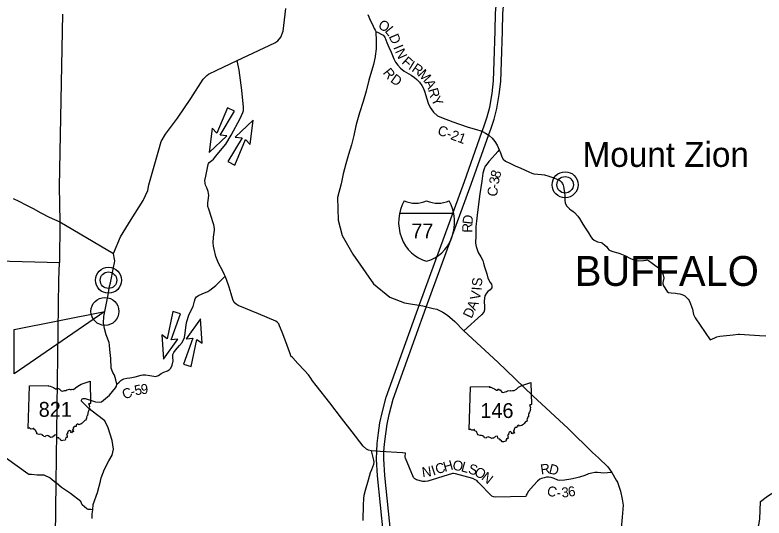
# Model space of a CAD drawing. Extents: x 0 to 34, y 0 to 22.
# Drawn here: x 24.277 to 28.547, y 14.868 to 17.734 of the extents above; entities that cross this region are included whole.
import ezdxf

# ---------------------------------------------------------------- set-up
doc = ezdxf.new("R2010")
doc.units = 0
for name, color, linetype in [('Default', 7, 'Continuous'), ('GM_X_County_Road', 7, 'Continuous'), ('GM_X_County_Road_Text', 7, 'Continuous'), ('GM_X_Major_River', 7, 'Continuous'), ('GM_X_State_Route', 7, 'Continuous'), ('GM_X_Township', 7, 'Continuous'), ('GM_X_Unincorporated', 7, 'Continuous'), ('GM_X_Unincorporated_Text', 7, 'Continuous'), ('TX_P_1', 7, 'Continuous')]:
    doc.layers.add(name, color=color, linetype=linetype)

msp = doc.modelspace()

# ---------------------------------------------------------------- linework, layer by layer
at = {"layer": 'Default'}
for p, q in [((24.3527, 15.3778), (24.3606, 15.6218)), ((26.8657, 15.371), (26.8735, 15.615))]:
    msp.add_line(p, q, dxfattribs=at)
for points in [[(26.3336, 17.6392), (26.343, 17.6361), (26.3692, 17.6237), (26.3767, 17.6184), (26.3857, 17.6081), (26.3971, 17.5769), (26.4074, 17.5504), (26.4207, 17.5226), (26.4365, 17.4842), (26.4465, 17.4652), (26.4591, 17.4473), (26.4741, 17.4317), (26.4962, 17.4144), (26.5351, 17.3902), (26.5554, 17.3772), (26.5677, 17.3661), (26.5827, 17.3504), (26.5964, 17.3329), (26.6035, 17.3196), (26.6116, 17.2991), (26.624, 17.2562), (26.6324, 17.2319), (26.6446, 17.2064), (26.6636, 17.1805), (26.6864, 17.1603), (26.7093, 17.1491), (26.7724, 17.1261), (26.854, 17.0958), (26.9127, 17.0805), (26.9277, 17.0754), (26.9412, 17.0692), (26.9588, 17.0602), (26.9806, 17.0473), (26.9963, 17.032), (27.0131, 17.0122), (27.025, 16.9928), (27.0379, 16.9662)], [(25.4746, 16.2459), (25.4722, 16.2542), (25.4611, 16.2741), (25.4378, 16.3201), (25.4224, 16.3575), (25.4119, 16.3994), (25.4084, 16.4168), (25.4067, 16.4357), (25.4095, 16.4679), (25.4149, 16.5088), (25.4152, 16.5171), (25.4102, 16.5387), (25.392, 16.5972), (25.3885, 16.6104), (25.3823, 16.6281), (25.377, 16.6425), (25.3765, 16.6531), (25.3768, 16.6641), (25.38, 16.6906), (25.3818, 16.7069), (25.381, 16.7175), (25.3786, 16.7284), (25.3709, 16.7495), (25.3629, 16.7642), (25.3606, 16.7758), (25.3585, 16.791), (25.3644, 16.8159), (25.3787, 16.8827), (25.3802, 16.8869), (25.3844, 16.8933), (25.3913, 16.8996), (25.3996, 16.9056), (25.4091, 16.9127), (25.4218, 16.9288), (25.468, 16.984), (25.479, 16.9975), (25.5097, 17.0491), (25.5601, 17.145), (25.5763, 17.1782), (25.5798, 17.1906), (25.58, 17.208), (25.5697, 17.3065), (25.5542, 17.419), (25.5441, 17.4745)], [(27.0379, 16.9662), (27.0288, 16.9568), (26.9829, 16.9035), (26.9792, 16.8992)], [(27.0379, 16.9662), (27.0423, 16.954), (27.0478, 16.9373), (27.053, 16.9252), (27.0604, 16.9126), (27.0735, 16.9015), (27.0979, 16.8888), (27.129, 16.8741), (27.1598, 16.8609), (27.2053, 16.8397), (27.2233, 16.8319), (27.2342, 16.8292), (27.2579, 16.8267), (27.2779, 16.8254), (27.2949, 16.8225), (27.3201, 16.8151), (27.3494, 16.8065), (27.3667, 16.7991), (27.3768, 16.7945), (27.3837, 16.7901), (27.3906, 16.7828), (27.3981, 16.7746), (27.4012, 16.7648), (27.404, 16.7559)], [(26.9792, 16.8992), (26.9791, 16.899), (26.9681, 16.8863), (26.9581, 16.872), (26.9508, 16.8573), (26.9437, 16.8324), (26.9384, 16.7867), (26.9262, 16.7147), (26.9137, 16.6104), (26.9074, 16.5592), (26.9045, 16.5281), (26.9039, 16.4774), (26.9027, 16.4331), (26.9053, 16.4146), (26.9172, 16.3811), (26.9332, 16.356), (26.9434, 16.3343), (26.9478, 16.3203), (26.9542, 16.2996), (26.9662, 16.2582), (26.9734, 16.2349), (26.986, 16.2101), (26.9926, 16.2), (26.9961, 16.1883), (26.9959, 16.1789), (26.9859, 16.1674), (26.9721, 16.1576), (26.9643, 16.1492), (26.9551, 16.1343), (26.9515, 16.1047), (26.9536, 16.0691), (26.9528, 16.0532), (26.9503, 16.0403), (26.9362, 16.0264), (26.8359, 15.9347)], [(27.404, 16.7559), (27.4064, 16.7457), (27.4103, 16.72), (27.412, 16.7053), (27.4112, 16.686), (27.411, 16.6765), (27.4139, 16.663), (27.4214, 16.6468), (27.4372, 16.6301), (27.4475, 16.6219), (27.4567, 16.6164), (27.4663, 16.6083), (27.4847, 16.5885), (27.4952, 16.5736), (27.5084, 16.5522), (27.5243, 16.5275), (27.5457, 16.492), (27.559, 16.4706), (27.5678, 16.4606), (27.579, 16.4509), (27.5976, 16.4422), (27.6185, 16.4373), (27.6254, 16.434), (27.6403, 16.4233), (27.6503, 16.4125), (27.6569, 16.4043), (27.6623, 16.3968), (27.6707, 16.3916), (27.6855, 16.3858), (27.7144, 16.3792), (27.7246, 16.3752), (27.7528, 16.3643), (27.7852, 16.3468), (27.805, 16.3384), (27.8168, 16.3371), (27.8315, 16.334), (27.8591, 16.3345), (27.8746, 16.3378), (27.8798, 16.3386), (27.8875, 16.3354), (27.91, 16.3191), (27.9537, 16.287), (27.9595, 16.281), (27.9677, 16.2653), (27.9724, 16.2521), (27.9748, 16.2442), (27.975, 16.2336), (27.9715, 16.218), (27.9701, 16.2097), (27.9706, 16.2017), (27.9735, 16.1908), (27.9952, 16.1583), (28.0032, 16.1531), (28.0169, 16.1507), (28.0426, 16.1485), (28.0525, 16.1468), (28.0665, 16.1448), (28.0832, 16.1398), (28.0946, 16.1347), (28.1043, 16.125), (28.1139, 16.115), (28.1197, 16.1067), (28.1287, 16.088), (28.1383, 16.0579), (28.1424, 16.0364), (28.1452, 16.0273), (28.1546, 16.0093), (28.2395, 15.8837), (28.2501, 15.8865), (28.2696, 15.8963), (28.2782, 15.9003), (28.2959, 15.9036), (28.3702, 15.9125), (28.3989, 15.9153), (28.4076, 15.9162), (28.5215, 15.9069), (28.557, 15.9064)], [(24.2666, 16.6893), (24.2993, 16.6724), (24.3429, 16.6507), (24.3816, 16.6308), (24.4253, 16.6075), (24.4723, 16.582), (24.5329, 16.556)], [(24.5329, 16.556), (24.8396, 16.3747)], [(24.8568, 15.6314), (24.8705, 15.6419), (24.8807, 15.6515), (24.8859, 15.6557), (24.8976, 15.6603), (24.9149, 15.665), (24.9327, 15.6663), (24.9433, 15.6679), (24.9617, 15.6714), (24.9972, 15.6823), (25.0055, 15.6839), (25.0202, 15.684), (25.0467, 15.6808), (25.0686, 15.6757), (25.0766, 15.675), (25.0841, 15.6758), (25.0958, 15.6808), (25.1105, 15.6904), (25.1251, 15.6988), (25.147, 15.7073), (25.1564, 15.712), (25.1658, 15.7211), (25.1729, 15.7382), (25.1783, 15.764), (25.1767, 15.7844), (25.1773, 15.7988), (25.1818, 15.8113), (25.193, 15.8247), (25.2155, 15.8502), (25.2305, 15.8685), (25.2428, 15.8962), (25.2475, 15.9205), (25.2525, 15.9678), (25.2565, 15.9879), (25.2687, 16.024), (25.2784, 16.0441), (25.2922, 16.0726), (25.301, 16.1029), (25.3043, 16.117), (25.3114, 16.1276), (25.3223, 16.1364), (25.3449, 16.1457), (25.3758, 16.1588), (25.3882, 16.1657), (25.4213, 16.1936), (25.4746, 16.2459)], [(26.504, 15.2085), (26.5039, 15.2086), (26.5019, 15.2132), (26.5011, 15.2181), (26.5025, 15.2382), (26.4866, 15.2396), (26.3596, 15.2475), (26.309, 15.2507), (26.2931, 15.2547), (26.2817, 15.2599), (26.2623, 15.2779), (26.1983, 15.3588), (26.1384, 15.4363), (26.0721, 15.5232), (25.9935, 15.6229), (25.9733, 15.6503), (25.963, 15.6639), (25.9493, 15.6831), (25.9279, 15.709), (25.8899, 15.7481), (25.8602, 15.78), (25.8571, 15.7842), (25.8503, 15.7909), (25.848, 15.7996), (25.8383, 15.8237), (25.8275, 15.8573), (25.8006, 15.926), (25.7856, 15.9634), (25.7802, 15.9735), (25.7741, 15.9822), (25.7643, 15.9889), (25.665, 16.0313), (25.5498, 16.0796), (25.5373, 16.0867), (25.5262, 16.0957), (25.5182, 16.1126), (25.51, 16.1451), (25.4984, 16.184), (25.4822, 16.2278), (25.4746, 16.2459)], [(24.3606, 15.6218), (24.4687, 15.6233), (24.4671, 15.6204), (24.4772, 15.6198), (24.4881, 15.6146), (24.4973, 15.6113), (24.5084, 15.6036), (24.5152, 15.6036), (24.518, 15.61), (24.5231, 15.6051), (24.5293, 15.6042), (24.5398, 15.5925), (24.5486, 15.59), (24.559, 15.594), (24.5667, 15.5947), (24.5724, 15.5986), (24.5873, 15.602), (24.5915, 15.5999), (24.5993, 15.6004), (24.6033, 15.6019), (24.6102, 15.6005), (24.6221, 15.6094), (24.6346, 15.6199), (24.6537, 15.6298), (24.6822, 15.6391), (24.7048, 15.6474), (24.7081, 15.5208)], [(26.8735, 15.615), (26.9817, 15.6166), (26.98, 15.6136), (26.9902, 15.613), (27.0011, 15.6078), (27.0102, 15.6045), (27.0214, 15.5968), (27.0281, 15.5968), (27.031, 15.6032), (27.0361, 15.5983), (27.0422, 15.5974), (27.0528, 15.5857), (27.0615, 15.5832), (27.072, 15.5872), (27.0797, 15.5879), (27.0854, 15.5918), (27.1003, 15.5952), (27.1044, 15.5932), (27.1123, 15.5936), (27.1163, 15.5951), (27.1231, 15.5938), (27.1351, 15.6027), (27.1476, 15.6131), (27.1667, 15.623), (27.1952, 15.6323), (27.2178, 15.6407), (27.2211, 15.514)], [(24.7081, 15.5208), (24.7048, 15.519), (24.6996, 15.5198), (24.6961, 15.5164), (24.7004, 15.5104), (24.7024, 15.5041), (24.7006, 15.4973), (24.7024, 15.4916), (24.7012, 15.4868), (24.698, 15.482), (24.6968, 15.4775), (24.6941, 15.4728), (24.6943, 15.4701), (24.6917, 15.468), (24.6921, 15.4601), (24.6908, 15.4557), (24.6913, 15.4519), (24.6869, 15.4509), (24.6879, 15.4478), (24.6852, 15.4453), (24.6858, 15.4412), (24.6827, 15.4385), (24.6857, 15.4332), (24.6833, 15.4315), (24.6813, 15.4251), (24.6758, 15.4237), (24.6648, 15.412), (24.6609, 15.4075), (24.6566, 15.4064), (24.6541, 15.4018), (24.6488, 15.4018), (24.6406, 15.3986), (24.6354, 15.4041), (24.6262, 15.3975), (24.6251, 15.3899), (24.6136, 15.3901), (24.614, 15.3863), (24.6114, 15.3851), (24.609, 15.3813), (24.6104, 15.3744), (24.6049, 15.3727), (24.6056, 15.3687), (24.6091, 15.3663), (24.6106, 15.3587), (24.6048, 15.3602), (24.6001, 15.3538), (24.5952, 15.3553), (24.5968, 15.3608), (24.5885, 15.3673), (24.5808, 15.3621), (24.5767, 15.3537), (24.5766, 15.3481), (24.5708, 15.3447), (24.5746, 15.3368), (24.5738, 15.3313), (24.574, 15.3261), (24.5667, 15.3263), (24.5623, 15.3123)], [(27.2211, 15.514), (27.2177, 15.5123), (27.2126, 15.5131), (27.2091, 15.5096), (27.2134, 15.5036), (27.2154, 15.4974), (27.2136, 15.4905), (27.2154, 15.4848), (27.2142, 15.48), (27.211, 15.4752), (27.2098, 15.4708), (27.207, 15.466), (27.2072, 15.4633), (27.2046, 15.4613), (27.2051, 15.4533), (27.2038, 15.4489), (27.2042, 15.4451), (27.1999, 15.4442), (27.2009, 15.441), (27.1982, 15.4386), (27.1988, 15.4344), (27.1957, 15.4318), (27.1986, 15.4265), (27.1963, 15.4248), (27.1943, 15.4183), (27.1887, 15.417), (27.1778, 15.4052), (27.1739, 15.4007), (27.1696, 15.3996), (27.1671, 15.395), (27.1618, 15.395), (27.1536, 15.3918), (27.1484, 15.3973), (27.1392, 15.3907), (27.1381, 15.3831), (27.1265, 15.3833), (27.1269, 15.3795), (27.1243, 15.3784), (27.122, 15.3745), (27.1233, 15.3677), (27.1179, 15.3659), (27.1185, 15.362), (27.1221, 15.3596), (27.1236, 15.3519), (27.1178, 15.3535), (27.1131, 15.3471), (27.1082, 15.3486), (27.1098, 15.354), (27.1015, 15.3606), (27.0937, 15.3553), (27.0897, 15.3469), (27.0896, 15.3413), (27.0838, 15.3379), (27.0875, 15.33), (27.0868, 15.3245), (27.0869, 15.3193), (27.0797, 15.3195), (27.0752, 15.3055)], [(24.5623, 15.3123), (24.5497, 15.3096), (24.541, 15.308), (24.5378, 15.3144), (24.5316, 15.3177), (24.5275, 15.3241), (24.5185, 15.325), (24.5164, 15.3338), (24.5154, 15.3409), (24.5031, 15.3392), (24.4997, 15.3348), (24.4953, 15.3336), (24.4928, 15.3292), (24.4868, 15.3289), (24.4804, 15.3268), (24.4762, 15.3311), (24.4658, 15.3354), (24.4611, 15.3376), (24.4512, 15.3342), (24.4492, 15.3301), (24.4414, 15.3319), (24.4395, 15.3365), (24.4348, 15.3379), (24.4337, 15.3427), (24.4236, 15.3453), (24.4158, 15.3443), (24.4022, 15.3482), (24.4013, 15.3546), (24.3967, 15.3624), (24.3943, 15.3678), (24.3857, 15.3719), (24.3839, 15.3783), (24.3812, 15.3782), (24.3786, 15.3755), (24.369, 15.3743), (24.3652, 15.3769), (24.3598, 15.3815), (24.3527, 15.3778)], [(27.0752, 15.3055), (27.0627, 15.3028), (27.0539, 15.3012), (27.0508, 15.3076), (27.0446, 15.311), (27.0404, 15.3173), (27.0315, 15.3182), (27.0293, 15.327), (27.0283, 15.3341), (27.016, 15.3324), (27.0127, 15.328), (27.0083, 15.3269), (27.0058, 15.3224), (26.9998, 15.3221), (26.9934, 15.32), (26.9892, 15.3243), (26.9788, 15.3287), (26.974, 15.3309), (26.9642, 15.3274), (26.9621, 15.3233), (26.9544, 15.3251), (26.9525, 15.3297), (26.9478, 15.3311), (26.9467, 15.3359), (26.9366, 15.3386), (26.9288, 15.3375), (26.9152, 15.3414), (26.9143, 15.3478), (26.9096, 15.3556), (26.9073, 15.361), (26.8987, 15.3651), (26.8969, 15.3716), (26.8941, 15.3714), (26.8916, 15.3688), (26.882, 15.3675), (26.8782, 15.3702), (26.8728, 15.3747), (26.8657, 15.371)], [(26.2626, 14.854), (26.2639, 14.943), (26.2652, 14.9778), (26.2684, 14.9983), (26.275, 15.026), (26.2924, 15.0848), (26.3042, 15.1269), (26.312, 15.1451), (26.3235, 15.1747), (26.3253, 15.1842), (26.3233, 15.1978), (26.3148, 15.2272), (26.309, 15.2507)], [(24.2294, 15.2095), (24.3496, 15.122), (24.3561, 15.1184), (24.3716, 15.1183), (24.4042, 15.1143), (24.4419, 15.1146), (24.4786, 15.097), (24.5114, 15.0682)], [(27.6786, 15.128), (27.6553, 15.125), (27.6311, 15.1236), (27.6175, 15.1247), (27.5975, 15.1268), (27.5831, 15.1263), (27.5658, 15.1239), (27.5461, 15.1188), (27.525, 15.1107), (27.4949, 15.1002), (27.4723, 15.0955), (27.4447, 15.0885), (27.4092, 15.0841), (27.3813, 15.0819), (27.3718, 15.0834), (27.3502, 15.0927), (27.3336, 15.0978), (27.3192, 15.1004), (27.3071, 15.0999), (27.2932, 15.0975), (27.2788, 15.0933), (27.2694, 15.0883), (27.2551, 15.0776), (27.2319, 15.0539), (27.2045, 15.0208), (27.1967, 15.0078), (27.1915, 14.9983), (27.1885, 14.9911), (27.0136, 14.9871), (27.0041, 14.9882), (26.9947, 14.9923), (26.9178, 15.0726), (26.909, 15.0813), (26.901, 15.0861), (26.887, 15.0928), (26.7878, 15.1204), (26.7776, 15.1219), (26.7716, 15.1211), (26.6313, 15.0783), (26.6155, 15.0752), (26.6019, 15.0755), (26.5652, 15.0854), (26.5602, 15.0884), (26.5556, 15.091), (26.5496, 15.0993), (26.504, 15.2085)], [(24.72, 14.9136), (24.7095, 14.9155), (24.7033, 14.916), (24.6935, 14.9173), (24.6871, 14.9203), (24.6593, 14.9427), (24.6517, 14.9616), (24.5941, 15.008), (24.5423, 15.0424), (24.5114, 15.0682)], [(28.5032, 14.3125), (28.5032, 14.3126), (28.5041, 14.3199), (28.5022, 14.335), (28.4942, 14.363), (28.4916, 14.3835), (28.493, 14.424), (28.4964, 14.4614), (28.4975, 14.4788), (28.4982, 14.5681), (28.497, 14.6499), (28.4955, 14.6639), (28.4856, 14.7097), (28.4811, 14.7392), (28.4811, 14.7513), (28.4837, 14.7653), (28.4973, 14.7899), (28.5094, 14.8088), (28.518, 14.8297), (28.5237, 14.8622), (28.5275, 14.9622)]]:
    msp.add_lwpolyline(points, dxfattribs=at)
for centre, major_axis, start_param, end_param in [((26.6701, 16.5539), (0, -0.2289), 4.15077, 6.05619), ((26.5597, 16.844), (0, -0.1826), 5.88324, 6.683049), ((26.5773, 16.5539), (0, -0.2289), 0.227007, 2.13242), ((26.6877, 16.844), (0, -0.1827), 5.883359, 6.683012)]:
    msp.add_ellipse(centre, major_axis=major_axis, ratio=0.9, start_param=start_param, end_param=end_param, dxfattribs=at)
at = {"layer": 'GM_X_County_Road'}
msp.add_lwpolyline([(28.5275, 14.9622), (28.5597, 14.9867), (28.5772, 14.9995), (28.5967, 15.0123), (28.6146, 15.0236), (28.6224, 15.0313), (28.6301, 15.0455), (28.6374, 15.0827), (28.6426, 15.1331), (28.6476, 15.193), (28.6535, 15.2215), (28.6702, 15.2604), (28.7008, 15.3053), (28.709, 15.3119), (28.718, 15.3169), (28.7515, 15.324), (28.7674, 15.3287), (28.7746, 15.3291)], dxfattribs=at)
at = {"layer": 'GM_X_Major_River'}
msp.add_line((26.4698, 16.6053), (26.778, 16.6053), dxfattribs=at)
at = {"layer": 'GM_X_State_Route'}
for points in [[(26.5826, 16.084), (26.839, 16.7847), (26.9392, 17.0672), (26.9517, 17.1025), (26.9691, 17.1529), (26.9833, 17.2094), (26.9966, 17.287), (27.0052, 17.3586), (27.008, 17.4687), (27.0141, 17.6436), (27.0171, 17.7452), (27.0258, 17.8505), (27.0317, 17.9388), (27.0437, 18.0148), (27.0708, 18.149), (27.0918, 18.2474)], [(26.6216, 16.0697), (26.8781, 16.7706), (26.9784, 17.0533), (26.9909, 17.0888), (27.009, 17.141), (27.024, 17.2008), (27.0378, 17.281), (27.0467, 17.3556), (27.0496, 17.4674), (27.0557, 17.6423), (27.0587, 17.7428), (27.0673, 17.8474), (27.0731, 17.9341), (27.0846, 18.0075), (27.1116, 18.1405), (27.1325, 18.2388)], [(24.8396, 16.3747), (24.8787, 16.4704), (24.9397, 16.5684), (25.0078, 16.6764), (25.0352, 16.7337), (25.0404, 16.7663), (25.0857, 16.9267), (25.0968, 16.965), (25.1111, 17.0139), (25.1353, 17.0548), (25.2034, 17.1456), (25.2795, 17.2578), (25.3504, 17.3687), (25.3709, 17.3886), (25.3804, 17.3961), (25.4275, 17.4195), (25.5441, 17.4745), (25.7584, 17.5756), (25.7749, 17.5867), (25.792, 17.6078), (25.8049, 17.6409), (25.8218, 17.7707)], [(26.2879, 17.7372), (26.3039, 17.7007), (26.3125, 17.6833), (26.3251, 17.6578), (26.3306, 17.6483), (26.3336, 17.6392), (26.336, 17.5847), (26.3364, 17.5406), (26.3308, 17.4997), (26.3308, 17.4995)], [(26.3308, 17.4995), (26.3301, 17.4948), (26.3216, 17.4519), (26.295, 17.3622), (26.2787, 17.3007), (26.2624, 17.2419), (26.2417, 17.1769), (26.226, 17.1236), (26.2199, 17.1028), (26.2088, 17.0478), (26.1951, 16.9947), (26.1791, 16.9385), (26.1631, 16.8857), (26.1483, 16.8287), (26.1372, 16.7714), (26.1159, 16.6933), (26.1193, 16.5647), (26.1427, 16.4769), (26.2027, 16.3717), (26.3209, 16.2023), (26.4137, 16.1253), (26.4974, 16.0931), (26.6021, 16.0769), (26.6605, 16.0616), (26.6818, 16.0572), (26.7153, 16.0402), (26.7425, 16.0245), (26.7847, 15.9876), (26.8345, 15.9359), (26.8359, 15.9347), (27.0302, 15.755), (27.2293, 15.5647), (27.4311, 15.3777), (27.4322, 15.3766), (27.5698, 15.2412), (27.6037, 15.2112), (27.6566, 15.159), (27.6786, 15.128), (27.7043, 15.0833), (27.7112, 15.0713), (27.7281, 15.0212), (27.7374, 14.9753), (27.7432, 14.9416), (27.7378, 14.8727), (27.7316, 14.8094)], [(24.7174, 14.8651), (24.7179, 14.8913), (24.72, 14.9136), (24.7228, 14.9447), (24.7468, 15.013), (24.7651, 15.0771), (24.7677, 15.0975), (24.7868, 15.1458), (24.8115, 15.1933), (24.8308, 15.2252), (24.839, 15.2608), (24.8316, 15.3093), (24.8075, 15.3808), (24.7892, 15.422), (24.7417, 15.4581), (24.6992, 15.4901), (24.6745, 15.5143), (24.6612, 15.5278), (24.6567, 15.5339), (24.6563, 15.54), (24.6603, 15.546), (24.666, 15.5484), (24.6781, 15.548), (24.7194, 15.5349), (24.7354, 15.5293), (24.7591, 15.5283), (24.7704, 15.5299), (24.8154, 15.567), (24.8503, 15.6092), (24.8556, 15.6191), (24.8574, 15.6282), (24.8568, 15.6314), (24.8523, 15.6549), (24.8438, 15.681), (24.8347, 15.6977), (24.8263, 15.7215), (24.8227, 15.7764), (24.8179, 15.8272), (24.8159, 15.8533), (24.814, 15.8673), (24.796, 15.9108), (24.7876, 15.9482), (24.7821, 15.9774), (24.7839, 16.016), (24.808, 16.1404), (24.8166, 16.1882), (24.8207, 16.2085), (24.8385, 16.2948), (24.8442, 16.3223), (24.8463, 16.3323), (24.8432, 16.3523), (24.8396, 16.3747)], [(26.3777, 14.7733), (26.3443, 15.1077), (26.3384, 15.2036), (26.3389, 15.2484), (26.342, 15.2925), (26.3496, 15.3538), (26.3577, 15.4106), (26.3699, 15.4676), (26.3931, 15.5566), (26.5825, 16.0839)], [(26.4192, 14.7769), (26.3858, 15.111), (26.38, 15.2047), (26.3804, 15.2466), (26.3834, 15.2884), (26.3908, 15.3483), (26.3987, 15.4034), (26.4103, 15.458), (26.4329, 15.5443), (26.6216, 16.0699)]]:
    msp.add_lwpolyline(points, dxfattribs=at)
at = {"layer": 'GM_X_Township'}
for p, q in [((24.5489, 17.738), (24.5285, 16.7562)), ((24.5285, 16.7562), (24.5329, 16.556)), ((24.5329, 16.556), (24.5317, 16.3233)), ((23.5249, 16.3502), (24.5317, 16.3233)), ((24.527, 16.2224), (24.5317, 16.3233)), ((24.527, 16.2224), (24.5317, 16.3233)), ((24.527, 16.2224), (24.5317, 16.3233)), ((24.5114, 15.0682), (24.527, 16.2224)), ((24.5114, 15.0682), (24.527, 16.2224)), ((24.5027, 14.424), (24.5114, 15.0682))]:
    msp.add_line(p, q, dxfattribs=at)
at = {"layer": 'GM_X_Unincorporated'}
for centre, radius in [((27.413, 16.7666), 0.0742), ((27.413, 16.7666), 0.0471), ((24.8101, 16.2228), 0.0742), ((24.8101, 16.2228), 0.0471)]:
    msp.add_circle(centre, radius, dxfattribs=at)
at = {"layer": 'TX_P_1'}
for points in [[(25.5282, 17.1854), (25.4882, 17.2056), (25.4271, 17.0604), (25.4016, 17.0887), (25.3844, 16.9508), (25.4852, 17.0463), (25.4473, 17.0501)], [(25.6341, 17.1341), (25.5331, 17.0385), (25.5712, 17.0346), (25.4903, 16.8994), (25.5302, 16.8792), (25.5913, 17.0244), (25.6169, 16.9962)], [(24.2721, 15.9418), (24.7897, 16.045), (24.2721, 15.69)], [(25.2201, 16.0317), (25.1769, 16.0439), (25.1449, 15.8896), (25.1144, 15.9125), (25.1242, 15.7738), (25.2047, 15.8869), (25.1668, 15.8834)], [(25.3338, 16.0018), (25.2532, 15.8886), (25.2914, 15.8921), (25.2381, 15.7438), (25.2811, 15.7316), (25.313, 15.8859), (25.3436, 15.8632)]]:
    msp.add_lwpolyline(points, close=True, dxfattribs=at)
msp.add_circle((24.7897, 16.045), 0.0797, dxfattribs=at)

# ---------------------------------------------------------------- texts
at = {"layer": 'Default'}
for s, p in [('77', (26.5362, 16.461)), ('821', (24.4123, 15.4446)), ('146', (26.9299, 15.4378))]:
    msp.add_text(s, height=0.08462, dxfattribs=at).set_placement(p)
at = {"layer": 'GM_X_County_Road_Text'}
for s, rotation, p in [('O', 333.2183, (26.3426, 17.6602)), ('L', 308.7421, (26.3822, 17.6418)), ('D', 293.013, (26.4067, 17.6122)), ('I', 292.2949, (26.4327, 17.5503)), ('N', 294.0168, (26.4423, 17.527)), ('F', 317.8384, (26.4776, 17.4607)), ('I', 328.6139, (26.5153, 17.4281)), ('R', 308.5227, (26.3715, 17.4039)), ('R', 325.7882, (26.5345, 17.4164)), ('M', 312.863, (26.5705, 17.3924)), ('D', 324.605, (26.4129, 17.3558)), ('A', 296.6433, (26.6099, 17.3508)), ('R', 286.0151, (26.6313, 17.3088)), ('Y', 295.5868, (26.6478, 17.2543)), ('C-21', 339.725, (26.681, 17.0548)), ('8', 72.1493, (27.0389, 16.7993)), ('3', 82.7498, (27.0351, 16.7673)), ('C', 80.5787, (27.0235, 16.6961)), ('-', 80.9845, (27.0312, 16.7424)), ('D', 83.7366, (26.8839, 16.5385)), ('R', 88.9774, (26.8831, 16.4933)), ('S', 85.4814, (26.9378, 16.1858)), ('V', 79.2362, (26.926, 16.1064)), ('I', 86.0564, (26.9362, 16.1627)), ('A', 65.3128, (26.9006, 16.0468)), ('D', 64.9811, (26.8793, 16.0012)), ('5', 11.5896, (24.964, 15.5659)), ('9', 5.2261, (24.9966, 15.5727)), ('C', 21.1349, (24.9008, 15.5426)), ('-', 17.9532, (24.9435, 15.5591)), ('N', 7.6397, (26.6002, 15.1001)), ('I', 18.5685, (26.6611, 15.1094)), ('C', 17.0944, (26.6828, 15.1167)), ('H', 15.7673, (26.727, 15.1303)), ('O', 350.1304, (26.7684, 15.1435)), ('L', 344.5261, (26.8161, 15.1352)), ('S', 343.821, (26.8568, 15.124)), ('R', 8.3189, (27.2764, 15.1155)), ('D', 346.0159, (27.3167, 15.1225)), ('O', 329.9384, (26.8902, 15.1147)), ('N', 321.8215, (26.9316, 15.0909)), ('C', 345.1591, (27.305, 14.9988)), ('3', 5.0048, (27.3946, 14.9843)), ('6', 9.4377, (27.4341, 14.988)), ('-', 358.2349, (27.364, 14.9848))]:
    msp.add_text(s, height=0.0567, rotation=rotation, dxfattribs=at).set_placement(p)
at = {"layer": 'GM_X_Unincorporated_Text'}
for s, height, p in [('Mount Zion', 0.14175, (27.5125, 16.8684)), ('BUFFALO', 0.1701, (27.4682, 16.1905))]:
    msp.add_text(s, height=height, rotation=0, dxfattribs=at).set_placement(p)

doc.saveas('drawing.dxf')
